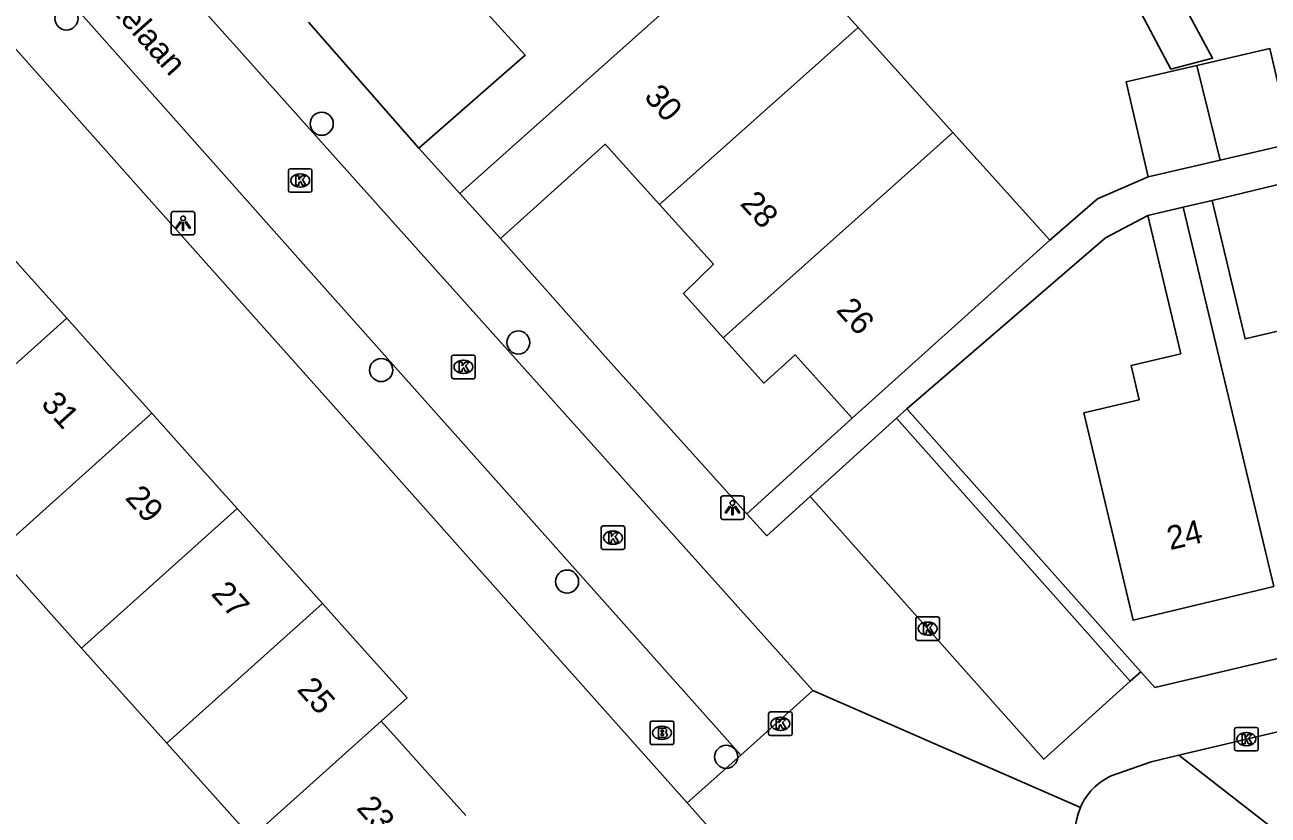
# Model space of a CAD drawing. Extents: x 158474 to 159560, y 388525 to 389605.
# Drawn here: x 159117.5 to 159170.2, y 388834 to 388867.5 of the extents above; entities that cross this region are included whole.
import ezdxf

# ---------------------------------------------------------------- set-up
doc = ezdxf.new("R2010")
doc.units = 0
for name, color, linetype in [('IMGEO_Boom', 7, 'Continuous'), ('IMGEO_Brandkraan', 7, 'Continuous'), ('IMGEO_Groenvoorziening', 7, 'Continuous'), ('IMGEO_Kolk', 7, 'Continuous'), ('IMGEO_Lichtpunt', 7, 'Continuous'), ('IMGEO_Openbare_ruimte_label', 7, 'Continuous'), ('IMGEO_Pand', 7, 'Continuous'), ('IMGEO_Pand_nummerreeks', 7, 'Continuous'), ('IMGEO_Rijbaan_lokaal_open', 7, 'Continuous'), ('IMGEO_Voetpad_open', 7, 'Continuous')]:
    doc.layers.add(name, color=color, linetype=linetype)

msp = doc.modelspace()

# ---------------------------------------------------------------- linework, layer by layer
at = {"layer": 'IMGEO_Boom'}
for centre in [(159119.261, 388867.72), (159130.079, 388863.261), (159138.413, 388853.987), (159132.6, 388852.82), (159140.479, 388843.855), (159147.221, 388836.425)]:
    msp.add_circle(centre, 0.489, dxfattribs=at)
at = {"layer": 'IMGEO_Brandkraan'}
for p, q in [((159143.999, 388837.015), (159143.999, 388837.867)), ((159144.074, 388837.941), (159144.926, 388837.941)), ((159144.487, 388837.721), (159144.512, 388837.721)), ((159145, 388837.867), (159145, 388837.015)), ((159144.926, 388836.941), (159144.074, 388836.941)), ((159144.51, 388837.161), (159144.485, 388837.161))]:
    msp.add_line(p, q, dxfattribs=at)
for points in [[(159143.999, 388837.015), (159143.999, 388837.867)], [(159144.074, 388837.941), (159144.926, 388837.941)], [(159145, 388837.867), (159145, 388837.015)], [(159144.347, 388837.641), (159144.347, 388837.241), (159144.56, 388837.241)], [(159144.578, 388837.641), (159144.347, 388837.641)], [(159144.526, 388837.56), (159144.472, 388837.56), (159144.472, 388837.484)], [(159144.472, 388837.484), (159144.525, 388837.484)], [(159144.534, 388837.408), (159144.472, 388837.408), (159144.472, 388837.327)], [(159144.472, 388837.327), (159144.534, 388837.327)], [(159144.926, 388836.941), (159144.074, 388836.941)]]:
    msp.add_lwpolyline(points, dxfattribs=at)
for centre, radius, start, end in [((159144.076, 388837.865), 0.0765, 91.552, 178.448), ((159144.076, 388837.865), 0.0765, 91.552, 178.448), ((159144.924, 388837.865), 0.0765, 1.552, 88.448), ((159144.924, 388837.865), 0.0765, 1.552, 88.448), ((159144.527, 388837.522), 0.0379, 267.8285, 90.9355), ((159144.535, 388837.367), 0.0404, 269.8759, 90.5077), ((159144.566, 388837.492), 0.251, 268.6676, 293.5347), ((159144.582, 388837.496), 0.145, 59.4692, 91.5367), ((159144.607, 388837.543), 0.0922, 285.5137, 58.1501), ((159144.612, 388837.351), 0.105, 301.3115, 78.989), ((159144.076, 388837.017), 0.0765, 181.552, 268.448), ((159144.076, 388837.017), 0.0765, 181.552, 268.448), ((159144.924, 388837.017), 0.0765, 271.552, 358.448), ((159144.924, 388837.017), 0.0765, 271.552, 358.448)]:
    msp.add_arc(centre, radius, start, end, dxfattribs=at)
for centre, major_axis, ratio, start_param, end_param in [((159144.486, 388837.441), (-0.387, 0.002), 0.722429, 4.712389, 7.853982), ((159144.511, 388837.441), (-0.39, 0.002), 0.717154, 1.570796, 4.712389)]:
    msp.add_ellipse(centre, major_axis=major_axis, ratio=ratio, start_param=start_param, end_param=end_param, dxfattribs=at)
at = {"layer": 'IMGEO_Groenvoorziening'}
msp.add_lwpolyline([(159182.441, 388840.288), (159178.325, 388827.216), (159166.412, 388836.499)], dxfattribs=at)
at = {"layer": 'IMGEO_Kolk'}
for p, q in [((159128.666, 388860.427), (159128.666, 388861.279)), ((159128.741, 388861.353), (159129.593, 388861.353)), ((159129.154, 388861.133), (159129.179, 388861.133)), ((159129.667, 388861.279), (159129.667, 388860.427)), ((159129.177, 388860.573), (159129.152, 388860.573)), ((159129.593, 388860.353), (159128.741, 388860.353)), ((159135.586, 388852.527), (159135.586, 388853.379)), ((159135.661, 388853.453), (159136.513, 388853.453)), ((159136.074, 388853.233), (159136.099, 388853.233)), ((159136.587, 388853.379), (159136.587, 388852.527)), ((159136.097, 388852.673), (159136.072, 388852.673)), ((159136.513, 388852.453), (159135.661, 388852.453)), ((159141.922, 388845.288), (159141.922, 388846.14)), ((159141.997, 388846.214), (159142.849, 388846.214)), ((159142.923, 388846.14), (159142.923, 388845.288)), ((159142.41, 388845.994), (159142.435, 388845.994)), ((159142.849, 388845.214), (159141.997, 388845.214)), ((159142.433, 388845.434), (159142.408, 388845.434)), ((159155.262, 388841.433), (159155.262, 388842.285)), ((159155.337, 388842.359), (159156.189, 388842.359)), ((159155.75, 388842.139), (159155.775, 388842.139)), ((159156.263, 388842.285), (159156.263, 388841.433)), ((159155.773, 388841.579), (159155.748, 388841.579)), ((159156.189, 388841.359), (159155.337, 388841.359)), ((159149.02, 388837.401), (159149.02, 388838.253)), ((159149.095, 388838.327), (159149.947, 388838.327)), ((159150.021, 388838.253), (159150.021, 388837.401)), ((159149.508, 388838.107), (159149.533, 388838.107)), ((159149.947, 388837.327), (159149.095, 388837.327)), ((159149.531, 388837.547), (159149.506, 388837.547)), ((159168.769, 388836.748), (159168.769, 388837.6)), ((159168.844, 388837.674), (159169.696, 388837.674)), ((159169.257, 388837.454), (159169.282, 388837.454)), ((159169.77, 388837.6), (159169.77, 388836.748)), ((159169.696, 388836.674), (159168.844, 388836.674)), ((159169.28, 388836.894), (159169.255, 388836.894))]:
    msp.add_line(p, q, dxfattribs=at)
for points in [[(159128.666, 388860.427), (159128.666, 388861.279)], [(159128.741, 388861.353), (159129.593, 388861.353)], [(159128.987, 388861.053), (159129.11, 388861.053), (159129.11, 388860.902), (159129.24, 388861.053), (159129.404, 388861.053), (159129.258, 388860.902), (159129.411, 388860.653), (159129.259, 388860.653), (159129.174, 388860.817), (159129.11, 388860.75), (159129.11, 388860.653), (159128.987, 388860.653), (159128.987, 388861.053)], [(159129.667, 388861.279), (159129.667, 388860.427)], [(159129.593, 388860.353), (159128.741, 388860.353)], [(159135.586, 388852.527), (159135.586, 388853.379)], [(159135.661, 388853.453), (159136.513, 388853.453)], [(159135.907, 388853.153), (159136.03, 388853.153), (159136.03, 388853.002), (159136.16, 388853.153), (159136.324, 388853.153), (159136.178, 388853.002), (159136.331, 388852.753), (159136.179, 388852.753), (159136.094, 388852.917), (159136.03, 388852.85), (159136.03, 388852.753), (159135.907, 388852.753), (159135.907, 388853.153)], [(159136.587, 388853.379), (159136.587, 388852.527)], [(159136.513, 388852.453), (159135.661, 388852.453)], [(159141.922, 388845.288), (159141.922, 388846.14)], [(159141.997, 388846.214), (159142.849, 388846.214)], [(159142.923, 388846.14), (159142.923, 388845.288)], [(159142.243, 388845.914), (159142.366, 388845.914), (159142.366, 388845.763), (159142.496, 388845.914), (159142.66, 388845.914), (159142.514, 388845.763), (159142.667, 388845.514), (159142.515, 388845.514), (159142.43, 388845.678), (159142.366, 388845.611), (159142.366, 388845.514), (159142.243, 388845.514), (159142.243, 388845.914)], [(159142.849, 388845.214), (159141.997, 388845.214)], [(159155.262, 388841.433), (159155.262, 388842.285)], [(159155.337, 388842.359), (159156.189, 388842.359)], [(159155.583, 388842.059), (159155.706, 388842.059), (159155.706, 388841.908), (159155.836, 388842.059), (159156, 388842.059), (159155.854, 388841.908), (159156.007, 388841.659), (159155.855, 388841.659), (159155.77, 388841.823), (159155.706, 388841.756), (159155.706, 388841.659), (159155.583, 388841.659), (159155.583, 388842.059)], [(159156.263, 388842.285), (159156.263, 388841.433)], [(159156.189, 388841.359), (159155.337, 388841.359)], [(159149.02, 388837.401), (159149.02, 388838.253)], [(159149.095, 388838.327), (159149.947, 388838.327)], [(159150.021, 388838.253), (159150.021, 388837.401)], [(159149.341, 388838.027), (159149.464, 388838.027), (159149.464, 388837.876), (159149.594, 388838.027), (159149.758, 388838.027), (159149.612, 388837.876), (159149.765, 388837.627), (159149.613, 388837.627), (159149.528, 388837.791), (159149.464, 388837.724), (159149.464, 388837.627), (159149.341, 388837.627), (159149.341, 388838.027)], [(159149.947, 388837.327), (159149.095, 388837.327)], [(159168.769, 388836.748), (159168.769, 388837.6)], [(159168.844, 388837.674), (159169.696, 388837.674)], [(159169.09, 388837.374), (159169.213, 388837.374), (159169.213, 388837.223), (159169.343, 388837.374), (159169.507, 388837.374), (159169.361, 388837.223), (159169.514, 388836.974), (159169.362, 388836.974), (159169.277, 388837.138), (159169.213, 388837.071), (159169.213, 388836.974), (159169.09, 388836.974), (159169.09, 388837.374)], [(159169.77, 388837.6), (159169.77, 388836.748)], [(159169.696, 388836.674), (159168.844, 388836.674)]]:
    msp.add_lwpolyline(points, dxfattribs=at)
for centre, start, end in [((159128.743, 388861.277), 91.552, 178.448), ((159128.743, 388861.277), 91.552, 178.448), ((159129.591, 388861.277), 1.552, 88.448), ((159129.591, 388861.277), 1.552, 88.448), ((159128.743, 388860.429), 181.552, 268.448), ((159128.743, 388860.429), 181.552, 268.448), ((159129.591, 388860.429), 271.552, 358.448), ((159129.591, 388860.429), 271.552, 358.448), ((159135.663, 388853.377), 91.552, 178.448), ((159135.663, 388853.377), 91.552, 178.448), ((159136.511, 388853.377), 1.552, 88.448), ((159136.511, 388853.377), 1.552, 88.448), ((159135.663, 388852.529), 181.552, 268.448), ((159135.663, 388852.529), 181.552, 268.448), ((159136.511, 388852.529), 271.552, 358.448), ((159136.511, 388852.529), 271.552, 358.448), ((159141.999, 388846.138), 91.552, 178.448), ((159141.999, 388846.138), 91.552, 178.448), ((159142.847, 388846.138), 1.552, 88.448), ((159142.847, 388846.138), 1.552, 88.448), ((159141.999, 388845.29), 181.552, 268.448), ((159141.999, 388845.29), 181.552, 268.448), ((159142.847, 388845.29), 271.552, 358.448), ((159142.847, 388845.29), 271.552, 358.448), ((159155.339, 388842.283), 91.552, 178.448), ((159155.339, 388842.283), 91.552, 178.448), ((159156.187, 388842.283), 1.552, 88.448), ((159156.187, 388842.283), 1.552, 88.448), ((159155.339, 388841.435), 181.552, 268.448), ((159155.339, 388841.435), 181.552, 268.448), ((159156.187, 388841.435), 271.552, 358.448), ((159156.187, 388841.435), 271.552, 358.448), ((159149.097, 388838.251), 91.552, 178.448), ((159149.097, 388838.251), 91.552, 178.448), ((159149.945, 388838.251), 1.552, 88.448), ((159149.945, 388838.251), 1.552, 88.448), ((159149.097, 388837.403), 181.552, 268.448), ((159149.097, 388837.403), 181.552, 268.448), ((159149.945, 388837.403), 271.552, 358.448), ((159149.945, 388837.403), 271.552, 358.448), ((159168.846, 388837.598), 91.552, 178.448), ((159168.846, 388837.598), 91.552, 178.448), ((159169.694, 388837.598), 1.552, 88.448), ((159169.694, 388837.598), 1.552, 88.448), ((159168.846, 388836.75), 181.552, 268.448), ((159168.846, 388836.75), 181.552, 268.448), ((159169.694, 388836.75), 271.552, 358.448), ((159169.694, 388836.75), 271.552, 358.448)]:
    msp.add_arc(centre, 0.0765, start, end, dxfattribs=at)
for centre, major_axis, ratio, start_param, end_param in [((159129.153, 388860.853), (-0.387, 0.002), 0.722429, 4.712389, 7.853982), ((159129.178, 388860.853), (-0.39, 0.002), 0.717154, 1.570796, 4.712389), ((159136.073, 388852.953), (-0.387, 0.002), 0.722429, 4.712389, 7.853982), ((159136.098, 388852.953), (-0.39, 0.002), 0.717154, 1.570796, 4.712389), ((159142.409, 388845.714), (-0.387, 0.002), 0.722429, 4.712389, 7.853982), ((159142.434, 388845.714), (-0.39, 0.002), 0.717154, 1.570796, 4.712389), ((159155.749, 388841.859), (-0.387, 0.002), 0.722429, 4.712389, 7.853982), ((159155.774, 388841.859), (-0.39, 0.002), 0.717154, 1.570796, 4.712389), ((159149.507, 388837.827), (-0.387, 0.002), 0.722429, 4.712389, 7.853982), ((159149.532, 388837.827), (-0.39, 0.002), 0.717154, 1.570796, 4.712389), ((159169.256, 388837.174), (-0.387, 0.002), 0.722429, 4.712389, 7.853982), ((159169.281, 388837.174), (-0.39, 0.002), 0.717154, 1.570796, 4.712389)]:
    msp.add_ellipse(centre, major_axis=major_axis, ratio=ratio, start_param=start_param, end_param=end_param, dxfattribs=at)
at = {"layer": 'IMGEO_Lichtpunt'}
for p, q in [((159123.704, 388859.447), (159123.704, 388858.64)), ((159123.704, 388859.447), (159123.704, 388858.64)), ((159124.606, 388859.542), (159123.798, 388859.542)), ((159124.606, 388859.542), (159123.798, 388859.542)), ((159124.7, 388858.64), (159124.7, 388859.447)), ((159124.7, 388858.64), (159124.7, 388859.447)), ((159123.798, 388858.546), (159124.606, 388858.546)), ((159123.798, 388858.546), (159124.606, 388858.546)), ((159146.99, 388847.386), (159146.99, 388846.579)), ((159146.99, 388847.386), (159146.99, 388846.579)), ((159147.892, 388847.481), (159147.084, 388847.481)), ((159147.892, 388847.481), (159147.084, 388847.481)), ((159147.986, 388846.579), (159147.986, 388847.386)), ((159147.986, 388846.579), (159147.986, 388847.386)), ((159147.084, 388846.485), (159147.892, 388846.485)), ((159147.084, 388846.485), (159147.892, 388846.485))]:
    msp.add_line(p, q, dxfattribs=at)
for points in [[(159124.078, 388859.111), (159124.117, 388859.083), (159123.929, 388858.821), (159123.891, 388858.848), (159124.078, 388859.111)], [(159124.18, 388859.063), (159124.227, 388859.063), (159124.227, 388858.741), (159124.18, 388858.741), (159124.18, 388859.063)], [(159124.29, 388859.083), (159124.328, 388859.11), (159124.515, 388858.848), (159124.476, 388858.82), (159124.29, 388859.083)], [(159147.364, 388847.05), (159147.403, 388847.022), (159147.215, 388846.76), (159147.177, 388846.787), (159147.364, 388847.05)], [(159147.466, 388847.002), (159147.513, 388847.002), (159147.513, 388846.68), (159147.466, 388846.68), (159147.466, 388847.002)], [(159147.576, 388847.022), (159147.614, 388847.049), (159147.801, 388846.787), (159147.762, 388846.759), (159147.576, 388847.022)]]:
    msp.add_lwpolyline(points, dxfattribs=at)
for centre in [(159124.203, 388859.245), (159147.489, 388847.184)]:
    msp.add_circle(centre, 0.0994, dxfattribs=at)
for centre, start, end in [((159123.798, 388859.447), 90, 180), ((159123.798, 388859.447), 90, 180), ((159124.606, 388859.447), 0, 90), ((159124.606, 388859.447), 0, 90), ((159123.798, 388858.64), 180, 270), ((159123.798, 388858.64), 180, 270), ((159124.606, 388858.64), 270, 0), ((159124.606, 388858.64), 270, 360), ((159147.084, 388847.386), 90, 180), ((159147.084, 388847.386), 90, 180), ((159147.892, 388847.386), 0, 90), ((159147.892, 388847.386), 0, 90), ((159147.084, 388846.579), 180, 270), ((159147.084, 388846.579), 180, 270), ((159147.892, 388846.579), 270, 0), ((159147.892, 388846.579), 270, 360)]:
    msp.add_arc(centre, 0.0946, start, end, dxfattribs=at)
at = {"layer": 'IMGEO_Pand'}
for points in [[(159134.197, 388862.229), (159137.36, 388864.99), (159138.7, 388866.16), (159136.273, 388868.854), (159142.498, 388874.462), (159145.845, 388870.748), (159146.64, 388869.865)], [(159146.64, 388869.865), (159148.802, 388871.796), (159152.813, 388867.343)], [(159146.64, 388869.865), (159135.932, 388860.303)], [(159152.813, 388867.343), (159144.398, 388859.837)], [(159152.813, 388867.343), (159156.827, 388862.888)], [(159167.168, 388865.727), (159170.268, 388866.444), (159171.199, 388862.416)], [(159165.101, 388861.006), (159164.17, 388865.034), (159167.168, 388865.727)], [(159168.155, 388861.713), (159167.168, 388865.727)], [(159156.827, 388862.888), (159154.666, 388860.957), (159148.47, 388855.42), (159147.094, 388854.187)], [(159156.827, 388862.888), (159160.94, 388858.323)], [(159135.932, 388860.303), (159134.197, 388862.229)], [(159144.398, 388859.837), (159142.096, 388862.392), (159140.774, 388861.201), (159137.654, 388858.391)], [(159171.199, 388862.416), (159168.155, 388861.713)], [(159168.155, 388861.713), (159165.101, 388861.006)], [(159137.654, 388858.391), (159135.932, 388860.303)], [(159147.094, 388854.187), (159145.41, 388856.057), (159146.682, 388857.302), (159144.398, 388859.837)], [(159166.595, 388859.722), (159167.813, 388860.012)], [(159167.813, 388860.012), (159169.213, 388854.142), (159171.492, 388854.685), (159171.821, 388853.308), (159174.171, 388853.868)], [(159170.433, 388843.639), (159164.47, 388842.217), (159162.375, 388851.002), (159164.729, 388851.563), (159164.384, 388853.011), (159166.488, 388853.512), (159165.093, 388859.364)], [(159165.093, 388859.364), (159166.595, 388859.722)], [(159170.433, 388843.639), (159166.595, 388859.722)], [(159115.654, 388859.053), (159117.398, 388857.107), (159119.27, 388855.019)], [(159160.94, 388858.323), (159158.787, 388856.383), (159158.717, 388856.32), (159157.764, 388855.461), (159152.563, 388850.775)], [(159119.27, 388855.019), (159112.67, 388849.103)], [(159119.27, 388855.019), (159121.216, 388852.847), (159122.884, 388850.986)], [(159152.563, 388850.775), (159150.145, 388853.459), (159148.823, 388852.268), (159147.094, 388854.187)], [(159116.284, 388845.07), (159122.884, 388850.986)], [(159122.884, 388850.986), (159124.619, 388849.049), (159126.499, 388846.951)], [(159119.899, 388841.036), (159126.499, 388846.951)], [(159126.499, 388846.951), (159128.363, 388844.871), (159130.113, 388842.918)], [(159119.899, 388841.036), (159116.284, 388845.07)], [(159130.113, 388842.918), (159123.513, 388837.003)], [(159130.113, 388842.918), (159131.767, 388841.073), (159133.696, 388838.92), (159132.598, 388837.935)], [(159123.513, 388837.003), (159119.899, 388841.036)], [(159127.097, 388833.004), (159132.598, 388837.935)], [(159132.598, 388837.935), (159132.71, 388837.81), (159133.13, 388837.342), (159134.444, 388835.875), (159136.181, 388833.936)], [(159127.097, 388833.004), (159126.954, 388833.163), (159126.791, 388833.344), (159123.513, 388837.003)]]:
    msp.add_lwpolyline(points, dxfattribs=at)
at = {"layer": 'IMGEO_Rijbaan_lokaal_open'}
for points in [[(159110.228, 388887.513), (159120.719, 388875.66), (159119.366, 388874.455), (159133.192, 388858.982), (159150.894, 388839.243)], [(159147.838, 388836.491), (159129.752, 388856.818), (159116.489, 388871.743)], [(159147.838, 388836.491), (159150.894, 388839.243)]]:
    msp.add_lwpolyline(points, dxfattribs=at)
at = {"layer": 'IMGEO_Voetpad_open'}
for points in [[(159057.955, 388848.239), (159075.248, 388861.255), (159101.461, 388880.986), (159114.746, 388866.089), (159116.239, 388867.395), (159118.458, 388864.905), (159121.85, 388861.096), (159125.655, 388856.825), (159129.047, 388853.017), (159132.779, 388848.828), (159136.171, 388845.02), (159145.569, 388834.47)], [(159166.361, 388868.78), (159167.835, 388866.038), (159166.072, 388865.577), (159163.421, 388870.568)], [(159134.197, 388862.229), (159129.513, 388867.558)], [(159176.697, 388862.154), (159167.813, 388860.012)], [(159165.101, 388861.006), (159162.959, 388860.073), (159160.94, 388858.323)], [(159154.884, 388851.174), (159163.302, 388858.424), (159165.093, 388859.364)], [(159148.101, 388846.729), (159145.662, 388849.419), (159142.199, 388853.263), (159137.654, 388858.391)], [(159154.443, 388850.775), (159154.884, 388851.174)], [(159164.789, 388840.034), (159154.884, 388851.174)], [(159148.101, 388846.729), (159152.563, 388850.775)], [(159150.781, 388847.462), (159154.443, 388850.775)], [(159154.443, 388850.775), (159164.344, 388839.638)], [(159150.781, 388847.462), (159148.944, 388845.799), (159148.101, 388846.729)], [(159164.344, 388839.638), (159160.683, 388836.325), (159150.781, 388847.462)], [(159190.104, 388845.191), (159165.384, 388839.365), (159164.789, 388840.034)], [(159164.789, 388840.034), (159164.344, 388839.638)], [(159166.412, 388836.499), (159182.441, 388840.288)], [(159150.894, 388839.243), (159162.233, 388834.277)], [(159145.569, 388834.47), (159147.838, 388836.491)], [(159163.537, 388835.614), (159165.229, 388836.219), (159166.412, 388836.499)], [(159145.569, 388834.47), (159146.543, 388833.376), (159126.969, 388815.855)]]:
    msp.add_lwpolyline(points, dxfattribs=at)
for centre, radius, start, end in [((159164.628, 388833.245), 2.608, 114.7356, 156.6962), ((159165.019, 388833.103), 3.023, 157.1583, 240.6656)]:
    msp.add_arc(centre, radius, start, end, dxfattribs=at)

# ---------------------------------------------------------------- texts
at = {"layer": 'IMGEO_Openbare_ruimte_label'}
msp.add_text('Charentelaan', height=1, rotation=311.6335, dxfattribs=at).set_placement((159118.334, 388871.226))
at = {"layer": 'IMGEO_Pand_nummerreeks'}
for s, rotation, p in [('30', 312.0203, (159143.702, 388864.373)), ('28', 312.0203, (159147.775, 388859.853)), ('26', 312.0205, (159151.845, 388855.335)), ('31', 311.864, (159118.144, 388851.36)), ('29', 311.864, (159121.711, 388847.38)), ('24', 13.414, (159166.034, 388845.181)), ('27', 311.864, (159125.353, 388843.316)), ('25', 311.8658, (159128.993, 388839.253)), ('23', 311.8658, (159131.514, 388834.23))]:
    msp.add_text(s, height=1, rotation=rotation, dxfattribs=at).set_placement(p)

doc.saveas('drawing.dxf')
